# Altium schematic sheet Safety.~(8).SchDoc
size A
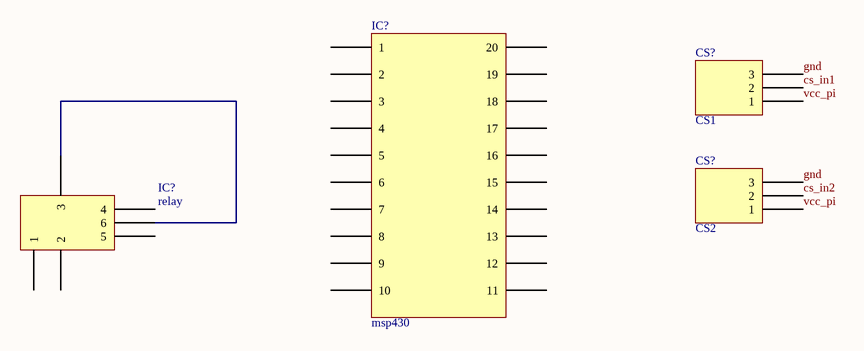
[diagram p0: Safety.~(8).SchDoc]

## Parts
(Parts that share a designator on the sheet are numbered #1, #2 ... from top to bottom, then left to right.)
CS?#1  CS1  [ACS712]
CS?#2  CS2  [ACS712]
IC?#1  msp430  [msp430]
IC?#2  relay  [relay JQX 15F]

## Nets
cs_in1: CS?#1.2
cs_in2: CS?#2.2
gnd: CS?#1.3 CS?#2.3
vcc_pi: CS?#1.1 CS?#2.1
NetIC?#2_3: IC?#2.3 IC?#2.6

Not connected (* = marked no-connect by the designer): IC?#1 1 2 3 4 5 6 7 8 9 10 11 12 13 14 15 16 17 18 19 20; IC?#2 1 2 4 5

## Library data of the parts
CS?#1 CS?#2 = ACS712
IC?#2 = relay JQX-15F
